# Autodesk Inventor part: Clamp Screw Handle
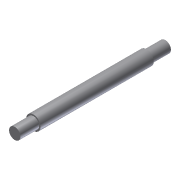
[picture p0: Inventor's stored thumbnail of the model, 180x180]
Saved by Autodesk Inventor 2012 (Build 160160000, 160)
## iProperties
Shininess: 77.0
Length Units: 11269
Angle Units: 11279
Time Units: 11290
Mass Units: 11283
Length Display Precision: 3
Angle Display Precision: 2
Compacted: True
Created: 2002-02
Part Number: Clamp Screw Handle
Document SubType Name: Modeling
Designer: ***
Density: 1 g/cm^3
Material: Default
Mass: 7.51155 g
Surface Area: 32.9239 cm^2
Volume: 7.51155 cm^3
Density: 0.0
Volumn: 0.0
Area: 0.0
PropertySet Name: Model Information
Control State: 0
Master: False
Checked Out: False
Author: ***
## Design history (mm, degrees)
sketch "Sketch1"
  geometry: L1 (0, 105)-(4, 105); L2 (4, 105)-(4, 92); L3 (4, 92)-(5, 92); L4 (5, 92)-(5, 13); L5 (5, 13)-(4, 13); L6 (4, 13)-(4, 0); L7 (4, 0)-(0, 0); L8 (0, 0)-(0, 105)
  constraints: 16 end point, 5 parallel, 2 equal length, 1 collinear, 1 horizontal, 1 perpendicular
  dimensions: "d0" = 10 diameter of L4 L8; "d1" = 8 diameter of L2 L8; "d2" = 13 distance of L1.end L2.end; "d3" = 79 distance of L3.end L4.end
revolve "Revolution1" sketch "Sketch1" stored, may be unused: angle "d4" = 90 deg
body "Solid1"
